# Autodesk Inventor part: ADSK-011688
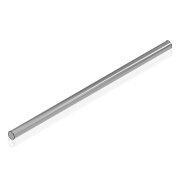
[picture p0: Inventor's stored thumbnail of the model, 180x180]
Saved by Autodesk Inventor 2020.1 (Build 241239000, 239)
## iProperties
Created: 2000-02
Part Number: ADSK-011688
Material: Pearson CD 1018
Document SubType Name: Modeling
Designer: glanglot
Density: 7.83 g/cm^3
Appearance: Chrom - poliert
Mass: 8231.35 g
Surface Area: 1128.28 cm^2
Volume: 1051.26 cm^3
Control State: 0
Checked Out: False
Master: False
Shininess: 60.0
Length Units: 11269
Angle Units: 11279
Time Units: 11290
Mass Units: 11283
Length Display Precision: 3
Angle Display Precision: 2
Compacted: True
Cutlength: 23.25
Material Desc: Material Description goes here
Material_Number: Pearson
Dimensions: 38x38x927 mm
Mass: 8,231 kg
DocNumber: ADSK-011688.ipt
Folder: 01 - Themengebiete\Simplification\01 - Packaging machine\ADSK-014200\Frame\
VDS_Category: 3D Komponenten
Density: 7.83
Volumn: 1056.979133710403
Area: 1132.4912157829076
PropertySet Name: Model Information
Author: glanglot
Revision Number: -
Title: shaft
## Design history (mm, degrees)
node "Solide1"
  node "Extrusion1" dims "d1" = 927, "d2" = 0
  node "Chamfer1" dims "d3" = 0.75, "d4" = 0.75, "d5" = 45 deg
sketch "Sketch1"
  geometry: C1 r 19 at (0, 0); 1 further point
  constraints: 1 centre point, 1 coincident
  dimensions: "d0" = 38 diameter of C1
node "Corps solides"
node "Corps surfaciques"
